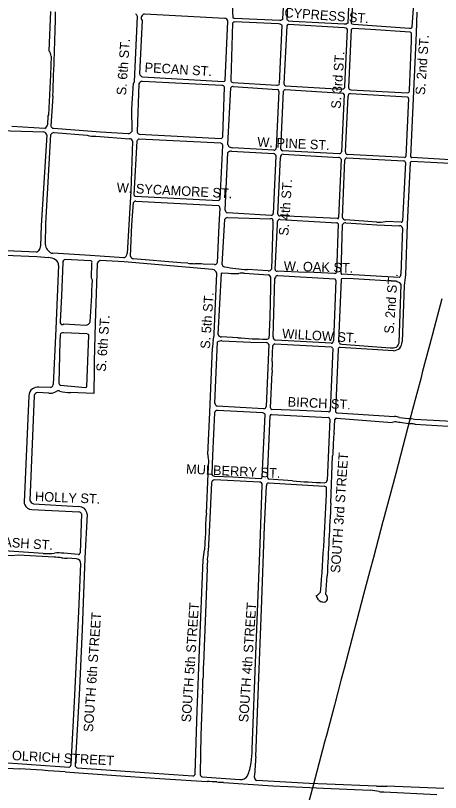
# Model space of a CAD drawing. Extents: x 0 to 712119, y 0 to 761125.
# Drawn here: x 686331 to 688555, y 729358 to 733421 of the extents above; entities that cross this region are included whole.
import ezdxf

# ---------------------------------------------------------------- set-up
doc = ezdxf.new("R2010")
doc.units = 0
for name, color, linetype in [('Arkansas-Missouri Railroad', 7, 'Continuous'), ('PAVED ROADS', 7, 'Continuous'), ('street names', 7, 'Continuous')]:
    doc.layers.add(name, color=color, linetype=linetype)

msp = doc.modelspace()

# ---------------------------------------------------------------- linework, layer by layer
at = {"layer": 'Arkansas-Missouri Railroad'}
msp.add_lwpolyline([(688562.9, 731940.1), (688522.3, 731786.8), (688511.6, 731746.8), (688511.6, 731746.8), (688460.2, 731553.5), (688460.2, 731553.5), (688453.5, 731528.4), (688409, 731360.2), (688409, 731360.2), (688384.7, 731268.3), (688357.9, 731166.8), (688357.9, 731166.8), (688320.9, 731026.5), (688306.8, 730973.4), (688306.8, 730973.4), (688255.4, 730780.1), (688255.4, 730780.1), (688254.2, 730775.6), (688204.3, 730586.7), (688204.3, 730586.7), (688185.6, 730516), (688153, 730393.4), (688153, 730393.4), (688117.3, 730258.8), (688101.8, 730200.1), (688101.8, 730200.1), (688050.7, 730006.7), (688050.7, 730006.7), (688035.8, 729950.2), (687999.7, 729813.3), (687999.7, 729813.3), (687960.2, 729663.3), (687948.6, 729619.9), (687948.6, 729619.9), (687918.6, 729508.1), (687896.9, 729426.7), (687896.9, 729426.7), (687888.3, 729394.3), (687836.8, 729201.1)], dxfattribs=at)
at = {"layer": 'PAVED ROADS'}
for points in [[(687737.6, 733555), (687729, 733403.1), (687728.8, 733398.6), (687721.9, 733396.3), (687719.8, 733394.8), (687714.6, 733394.3), (687477.6, 733405.4), (687474.6, 733405.5), (687471.3, 733405.7), (687470.5, 733408.6), (687468.1, 733441.7), (687474.9, 733589.4)], [(688075.8, 733508.1), (688069.7, 733380.6), (688067.4, 733379.5), (688061.5, 733376.4), (688058.5, 733375.1), (688051.7, 733375.1), (687781.9, 733390.3), (687762, 733392.2), (687757.4, 733394.4), (687754, 733397.3), (687752, 733400.8), (687759.1, 733547.1)], [(688412.9, 733458.7), (688404.5, 733359.3), (688402.7, 733354.9), (688398.1, 733353.3), (688393.5, 733352.8), (688100.1, 733374.7), (688093.8, 733375.6), (688091, 733376.6), (688089.5, 733378.7), (688097.7, 733504.4)], [(686514.4, 733442.8), (686506.1, 733237.2)], [(686954.5, 733075.5), (686968.7, 733415.8)], [(687426.6, 733405.7), (687006.6, 733428.9), (687006.6, 733428.9)], [(688400.4, 732682.7), (688429.5, 733329.2), (688433.6, 733438)], [(686993.5, 733395), (686979.2, 733117)], [(687429.1, 733081.5), (687442.3, 733392)], [(687473.6, 733387.1), (687472, 733386), (687470.4, 733384), (687467.4, 733381.3), (687457.4, 733084.6)], [(687712.5, 733064.7), (687727.3, 733369), (687722.3, 733373.2), (687716.6, 733375.9), (687707.8, 733377.3), (687476.4, 733388.2), (687473.6, 733387.1)], [(688053.9, 733050.8), (688068.2, 733348.6), (688064.7, 733352.5), (688061.3, 733355.3), (688050.3, 733357.4), (687759, 733374.6), (687757.1, 733373.7), (687754.9, 733372.4), (687750.4, 733367.7), (687735.5, 733063.7)], [(688092.9, 733352), (688089.5, 733349.6), (688088.2, 733347.2), (688074.3, 733044.7)], [(688393.7, 733030), (688402.8, 733288.7), (688403.9, 733329.4), (688400.9, 733332.6), (688397, 733334.3), (688189.7, 733347.7), (688097.7, 733353.4), (688092.9, 733352)], [(686517.1, 733208.7), (686513.7, 733111.1)], [(686513.7, 733111.1), (686503.4, 732901.2), (686500.9, 732895.7), (686499.1, 732849.5)], [(686995, 733099.9), (687419.6, 733075.2)], [(686940.9, 732816.1), (686939.6, 732932.6), (686949, 733067.6)], [(686976.1, 733063.6), (686967.5, 732812.6)], [(687410.8, 733055.5), (686994.8, 733076.5)], [(687416.4, 732789.7), (687425.1, 733046)], [(687442.7, 732746.9), (687457.6, 733042.8)], [(687468, 733071), (687697.8, 733056.2)], [(687469.9, 733049.2), (687701, 733034.7)], [(687744.5, 733053.9), (688041.3, 733036.4)], [(686526.1, 732999.8), (686516.6, 732842.9)], [(687709.8, 733025.8), (687695.6, 732728.6)], [(687720, 732721.9), (687734, 733025.1)], [(687742.2, 733033.6), (688043.5, 733015.6)], [(688050.3, 733008.8), (688036.5, 732708.2)], [(688058.6, 732707.8), (688071.9, 732998.6)], [(688083.9, 733012.8), (688380.1, 732995.5)], [(688085.2, 733032.5), (688383.3, 733017.1)], [(688387.8, 732986.9), (688374, 732684.4)], [(686483.6, 732830.6), (686310.9, 732840.4)], [(686186.2, 732821.2), (686479.6, 732812.4)], [(686495.5, 732795.3), (686465.8, 732323.5), (686462.3, 732214.7)], [(686488.6, 732222.6), (686490, 732332.5), (686515.2, 732799)], [(686529.1, 732831.5), (686775.3, 732813.4), (686920.1, 732804)], [(686532.4, 732808.6), (686706.3, 732795.2)], [(686978.9, 732801.2), (687407, 732778.2)], [(686751, 732789.8), (686927.3, 732776.1)], [(686943.9, 732763.9), (686934.2, 732502.1), (686923.7, 732327), (686915.4, 732175.8)], [(686966.6, 732764), (686949.9, 732484.8)], [(687404.8, 732752.9), (686977.8, 732774.9)], [(687401.3, 732462.4), (687415.8, 732741.5)], [(687683.3, 732717), (687467, 732729.9)], [(688027.2, 732698.5), (687728.9, 732714)], [(687428.7, 732402.4), (687441.4, 732702.8)], [(687460.9, 732712), (687682.3, 732700.1)], [(687694.3, 732686.3), (687679.7, 732385.6)], [(687704, 732382.4), (687717.5, 732678.6)], [(687732, 732695.9), (688021.6, 732679.3)], [(688064.8, 732676.7), (688363.7, 732661)], [(688367.5, 732678), (688068, 732694.7)], [(688665.2, 732662.8), (688405.5, 732677.8)], [(688034.7, 732669.8), (688021.8, 732364.3)], [(688043.1, 732364.8), (688054.3, 732666.6)], [(688396.8, 732653.1), (688381.4, 732330.5), (688372.9, 732064.2), (688365, 732009.3), (688354.4, 731713.9)], [(688372.6, 732653.2), (688356.9, 732347.4)], [(688672.1, 732643.9), (688403.5, 732657.9)], [(686956.4, 732475.8), (687395.5, 732453.6)], [(686933.3, 732161.7), (686940.5, 732326.6), (686948, 732442.4)], [(686960.5, 732450.4), (687392.6, 732426.6)], [(687400, 732414), (687395.8, 732324.7), (687385.9, 732128)], [(687669.7, 732376), (687440, 732388.9)], [(687413.2, 732119.1), (687424.3, 732325.5), (687425.7, 732354.3)], [(687440.1, 732365.1), (687665.6, 732358.1)], [(687678.4, 732349.6), (687677, 732326.3), (687670, 732095.2)], [(688016.9, 732358.7), (687715.2, 732373.3)], [(687716.6, 732354.8), (688011.9, 732336.9)], [(688221.6, 732340.8), (688057.9, 732352.7)], [(687689.1, 732092.8), (687701.6, 732328.7), (687702.4, 732343.9)], [(688018.9, 732331.5), (688010.3, 732077)], [(688034.9, 732074.1), (688041.7, 732327.9)], [(688060.5, 732337.1), (688222.7, 732325.9), (688341.2, 732321.6)], [(688349.1, 732340), (688266.9, 732343.2)], [(688356.9, 732308.3), (688348.3, 732068.4)], [(686441.3, 732184), (686163.8, 732196.3)], [(686512.2, 732181.9), (686496.2, 732197.9)], [(686158.2, 732168.7), (686276.7, 732167.9), (686442.8, 732160.2), (686502.8, 732155.5)], [(686898, 732154.2), (686721.4, 732165.3), (686526.1, 732177.7)], [(686724.2, 732138.7), (686590.3, 732145)], [(687233, 732125.2), (687196.1, 732127.9), (686947.3, 732148.5)], [(686556.6, 732113.4), (686541.9, 731782.3), (686528.5, 731490.5)], [(686578.8, 732130), (686571.1, 731955.8), (686565.5, 731820.7), (686565.4, 731814.5)], [(686733.7, 732037.4), (686728.1, 732048.2), (686731, 732127.6)], [(686757.6, 732122), (686748, 731812), (686742.7, 731612.2)], [(687361.8, 732092.4), (686898.9, 732132.3), (686773.9, 732139.4)], [(687373.1, 732119.3), (687312.5, 732120.9)], [(687371.1, 731756.4), (687385.3, 732072.4)], [(687390.8, 731753.1), (687409.7, 732072.7)], [(687412.7, 732075), (687445.5, 732073.1)], [(687527, 732074.3), (687654.3, 732064.4)], [(687653.2, 732085.2), (687544.9, 732092.6)], [(688000.1, 732071.1), (687858.9, 732078.1), (687847.9, 732076.3), (687699.9, 732083.5)], [(688339.1, 732050.4), (688039.6, 732068.1)], [(687678.8, 731740.2), (687688.8, 732046.8)], [(687703.8, 732060.8), (688001.9, 732044.2)], [(688007.5, 732035.3), (687994.5, 731720.2)], [(688035.7, 732039.9), (688021.9, 731719.6)], [(688324.6, 732029.2), (688100, 732043.7), (688042.1, 732045.7)], [(688338.4, 731708.9), (688349.5, 732015), (688343.1, 732023.4)], [(686583.9, 731808.1), (686698.3, 731801.7)], [(686564, 731750.1), (686562.6, 731716.7), (686557.4, 731497.8)], [(686705.8, 731755.4), (686582.2, 731761.9)], [(686704.7, 731481.4), (686715.2, 731747.8), (686715.2, 731747.8)], [(687493.8, 731736.1), (687409.3, 731740.4)], [(687374.3, 731393.8), (687388.7, 731713.9)], [(687411.1, 731720.4), (687562.7, 731712.1)], [(687562.7, 731712.1), (687642.8, 731710.2)], [(687657.2, 731699.6), (687643.1, 731375.9)], [(687688.8, 731703.3), (687982.4, 731688.6)], [(687983.3, 731707.2), (687692.7, 731723.4)], [(688027.2, 731709), (688028.7, 731703.3), (688038.9, 731702.9), (688292.3, 731682.8)], [(687337.8, 731125.9), (687347.8, 731344.1), (687362.2, 731684.5)], [(687673.8, 731612.2), (687677.3, 731695.8)], [(687992.3, 731678.9), (687978.6, 731355.9)], [(688019.2, 731674.4), (688005.3, 731352.7)], [(688309.8, 731667.7), (688029.8, 731684.8)], [(686743.4, 731567.4), (686740.1, 731444.8), (686618.4, 731449)], [(687665.7, 731368.9), (687674, 731554.1)], [(686513.7, 731474.8), (686452.6, 731478)], [(686562.5, 731456.9), (686562.5, 731456.9)], [(686566.6, 731488.1), (686697.9, 731476)], [(686400.2, 731431.9), (686375.6, 730875.8)], [(686427.9, 731434.1), (686406.7, 730884.4)], [(686504.8, 731445.7), (686446.4, 731449)], [(687631.4, 731363.6), (687506.8, 731370.4), (687386.3, 731378.4)], [(687371.9, 731343.3), (687362.6, 731120.3), (687357.8, 731024.8)], [(687625.6, 731342.6), (687388.8, 731355.8)], [(687621.7, 731006.7), (687636.8, 731334.2)], [(687671.3, 731334.2), (687966.6, 731319.5)], [(687968.6, 731347.8), (687817.2, 731354.6), (687672.5, 731360)], [(688015, 731343.1), (688314.2, 731323.3)], [(687649.5, 731008.5), (687663.6, 731327.9)], [(687975.5, 731310.4), (687961.3, 730989.1)], [(687998.3, 731236), (688002.7, 731307.7)], [(688011.8, 731314.9), (688303, 731293)], [(688344.2, 731293.5), (688388.7, 731288.1)], [(688404.2, 731313.3), (688418.4, 731309.7), (688650, 731297.9)], [(688421.9, 731283.1), (688653, 731269)], [(687330.4, 730818.4), (687340.1, 731024.4), (687343.2, 731095.6)], [(687981.5, 730869.9), (687990.9, 731117.9)], [(687371.9, 731012.1), (687468.5, 731007.7), (687614.1, 730999.6)], [(687356.3, 730977.2), (687345.5, 730756.2), (687339.9, 730620)], [(687607.6, 730980.7), (687373.3, 730992.8)], [(687569.9, 729583.1), (687583.8, 729946.1), (687599.7, 730346.5), (687612.1, 730658.2), (687622.4, 730965.5)], [(687655.3, 730976.6), (687947.7, 730958.7)], [(687779.9, 730987), (687656.8, 730996.3)], [(687588.3, 729544.1), (687601.6, 729867.7), (687617.8, 730316.7), (687634.7, 730749.2), (687643.8, 730962)], [(686424.3, 730867.7), (686661.2, 730852.4)], [(686415.5, 730837.9), (686662.6, 730825.2)], [(686705.6, 730813.1), (686694.1, 730582.5), (686679.1, 730211.5), (686665.8, 729901.6), (686643.9, 729500.7)], [(686676.3, 730814.2), (686668.6, 730610.3)], [(686533, 730587.4), (686344.7, 730599), (686312.5, 730595.8), (686092.2, 730612.1), (686092.2, 730612.1), (686092.2, 730612.1)], [(686475.8, 730606.7), (686321.8, 730618.7), (686099.5, 730633.2)], [(686660.1, 730603), (686584.1, 730608.5)], [(687271.3, 729457.1), (687281.3, 729782.2), (687294, 730104.1), (687312.7, 730575), (687320.4, 730626.7)], [(686650.9, 730579.8), (686601.6, 730582.8)], [(686622.3, 729503.8), (686641.9, 729865.8), (686662, 730304.1), (686672, 730552.5)], [(687334.7, 730528.4), (687327.1, 730342.4), (687317.1, 730075)], [(687955.9, 730392.2), (687962.2, 730490.5)], [(687309.8, 729894), (687301.3, 729655.8), (687299.2, 729559.4), (687297.3, 729454.9)], [(686215.9, 729518.1), (686610.9, 729490.3)], [(686047.6, 729496.3), (686148.9, 729492.4), (686351, 729481.2)], [(686591.3, 729464.9), (686711.2, 729456.2), (686906.1, 729443.3), (687112.6, 729428.9), (687333.8, 729414.2)], [(686654.3, 729487.2), (687006.2, 729462.4), (687259.7, 729444.3)], [(687307.5, 729440.1), (687505, 729425.7)], [(687419.2, 729410.5), (687677.1, 729392.9), (687835.5, 729385.6), (687942.6, 729380.1), (688188, 729369.8)], [(688219.7, 729390.1), (687960.5, 729401.8), (687868.5, 729404.5), (687592.2, 729419.9)], [(688573.4, 729378.6), (688275, 729389.7)], [(688259.1, 729360.7), (688537, 729347.1)]]:
    msp.add_lwpolyline(points, dxfattribs=at)
for centre, radius, start, end in [((663739.7, 733994.7), 22808.1, 357.49986, 358.60695), ((686949.8, 733412.8), 19.2, 9.1618, 58.286), ((687010, 733408.1), 21.1, 99.2689, 218.251), ((687427.8, 733391.2), 14.6, 3.0761, 94.6962), ((686450.8, 733199.4), 67, 8.0223, 34.3605), ((687003.9, 733124), 25.7, 195.7653, 249.6327), ((687417.9, 733087.9), 12.8, 277.4042, 330.322), ((687469.6, 733083.1), 12.3, 173.011, 262.7547), ((686944.5, 733076.6), 10, 296.4367, 353.8927), ((686996.7, 733053.6), 22.9, 94.6358, 154.1262), ((687411.8, 733041.5), 14.1, 18.7564, 93.9424), ((687467.1, 733039.6), 10, 73.7422, 161.268), ((687469.9, 733049.2), 0.0000011, 131.8261, 213.3101), ((687699.8, 733069.8), 13.7, 261.866, 337.8968), ((687747.6, 733065.6), 12.2, 188.9947, 255.2436), ((688042, 733048.5), 12.2, 266.6464, 10.7599), ((688086.5, 733044.6), 12.2, 179.3406, 264.2414), ((687700.6, 733025.5), 9.18, 2.1521, 87.7047), ((687742.2, 733025.3), 8.25, 90.28, 181.2573), ((687742.2, 733033.6), 0.000000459, 125.4465, 216.4238), ((688041.2, 733006.6), 9.31, 13.5004, 75.9329), ((688083.4, 733001.1), 11.7, 87.529, 192.3535), ((688382.4, 733028.4), 11.3, 274.5829, 7.8526), ((688380.3, 732988), 7.51, 351.0052, 91.6139), ((686468.1, 732859.1), 32.5, 298.5335, 342.7063), ((686530.2, 732845.3), 13.8, 189.8696, 265.4201), ((686473.5, 732790.7), 22.5, 11.7462, 74.198), ((686532.6, 732787.9), 20.7, 90.6397, 147.468), ((686743.8, 732918.7), 129.1, 253.0931, 273.2007), ((686920, 732828), 24, 270.0625, 330.4883), ((686980.1, 732813.8), 12.7, 185.7973, 264.6254), ((686930.1, 732762.6), 13.8, 5.2641, 101.7343), ((686980.1, 732761.3), 13.8, 99.4524, 168.6655), ((687405, 732789.5), 11.4, 280.0194, 1.3428), ((687403.9, 732741), 11.9, 2.3893, 85.6779), ((687457.4, 732747.5), 14.7, 182.1575, 256.3514), ((687468.3, 732762.3), 32.5, 243.8027, 267.6485), ((687684.4, 732728.2), 11.3, 264.5389, 1.7217), ((687729, 732723.1), 9.12, 187.8359, 269.3649), ((687462, 732684.2), 27.9, 92.3592, 137.9596), ((687676.5, 732682.9), 18.2, 10.8646, 71.3273), ((687731.4, 732681.7), 14.2, 87.3243, 192.5787), ((688020.8, 732664.4), 14.8, 21.007, 86.9823), ((688028.2, 732706.9), 8.39, 263.3011, 9.472), ((688071, 732659.7), 18, 109.8597, 157.5021), ((688069.3, 732705.5), 10.9, 167.9163, 263.0538), ((688364.3, 732687.8), 10.3, 288.2397, 340.76), ((688405.4, 732682.8), 4.99, 181.7658, 271.7039), ((688363.3, 732651.6), 9.37, 9.5136, 87.4724), ((688403.5, 732650.9), 7.02, 89.849, 161.7439), ((686960.5, 732485.6), 10.6, 184.2002, 247.1078), ((686961.1, 732435.6), 14.8, 92.1053, 152.3778), ((687389.4, 732463.9), 12, 300.5709, 352.5152), ((687389.4, 732416.2), 10.9, 347.9045, 72.6052), ((687443.6, 732403.5), 15, 183.9801, 255.9519), ((687445.6, 732342.7), 23.1, 103.7242, 149.7612), ((687668.9, 732349.2), 9.54, 2.6607, 110.2795), ((687669.8, 732385.9), 9.85, 269.364, 358.0687), ((687713.1, 732344.6), 10.7, 71.0499, 184.1993), ((687714.7, 732384.1), 10.8, 188.9318, 272.8171), ((687716.6, 732354.8), 0.000000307, 155.0566, 268.206), ((688017.3, 732363.3), 4.63, 265.0439, 11.8879), ((688055.8, 732365.3), 12.8, 182.1555, 279.4812), ((688350.4, 732346.4), 6.56, 258.2379, 8.005), ((688012.8, 732330.8), 6.23, 7.0972, 97.8996), ((688058.1, 732318.1), 19.1, 82.8678, 149.3543), ((688230.8, 732588.9), 248.3, 267.8757, 278.378), ((688341, 732305.5), 16.1, 9.9177, 89.2425), ((686429.3, 732214.1), 32.4, 291.7288, 327.1462), ((686422, 732217.3), 40.4, 328.9003, 356.2558), ((686523.2, 732219.7), 34.8, 175.2152, 218.8791), ((686496.7, 732072.9), 82.8, 58.6297, 85.7885), ((686526.3, 732203.6), 25.9, 236.8514, 269.4379), ((686522.3, 732114.2), 34.2, 358.6547, 59.2456), ((686592.9, 732131.1), 14.1, 100.7733, 184.2543), ((686891.1, 732177.6), 24.4, 286.4247, 355.8827), ((686951.3, 732166.8), 18.7, 195.9936, 257.8231), ((686723.2, 732130.5), 8.32, 339.7481, 83.1954), ((686785.8, 732112), 29.9, 113.323, 160.5148), ((687276.7, 732580.3), 457.2, 264.5167, 269.1634), ((687274.9, 731806.9), 316.2, 83.177, 90.8822), ((687375.3, 732129.8), 10.7, 258.4698, 350.2504), ((687423.4, 732117.5), 10.3, 171.4813, 274.7666), ((687574.7, 732838), 746, 258.3619, 267.7049), ((687359, 732065.3), 27.3, 15.2152, 83.9355), ((687414.8, 732069.1), 6.31, 109.6154, 145.3708), ((687477.4, 732422.1), 350.5, 264.7669, 273.6493), ((687521.1, 731965.4), 109, 86.9067, 101.3004), ((687654.7, 732101.7), 16.6, 264.8844, 336.9546), ((687652.2, 732049.6), 14.9, 350.7217, 81.9466), ((687700.4, 732095.1), 11.5, 191.5395, 267.7245), ((687999.8, 732083.5), 12.4, 271.5539, 328.0532), ((688039.9, 732073.1), 5.1, 169.4522, 266.4109), ((688325.6, 732068.7), 22.7, 306.4261, 359.371), ((665948.5, 733022.5), 20808.5, 356.68447, 357.28658), ((681230.5, 732058.4), 6436.6, 357.12783, 359.90003), ((687707, 732042.4), 18.7, 99.7091, 166.1886), ((687703.8, 732060.8), 0.00000149, 162.4192, 238.3628), ((687996.2, 732034.4), 11.4, 4.2025, 59.7547), ((688042.2, 732039.2), 6.5, 90.5124, 173.5126), ((688319.6, 731980.9), 48.6, 61.1231, 84.1622), ((686696.9, 731828.7), 27, 272.9682, 339.0287), ((686576.2, 731815.7), 10.8, 186.5825, 315.2937), ((686579.1, 731746.7), 15.5, 78.4552, 167.2145), ((686706.7, 731746.8), 8.61, 6.1261, 95.7883), ((686880.5, 731817), 494.3, 348.7611, 352.959), ((687410.3, 731761.6), 21.3, 203.6903, 267.3668), ((687695, 731739.5), 16.2, 177.4216, 262.1521), ((687602.7, 731682), 240.5, 170.7547, 179.4118), ((687420.3, 731647.9), 73.2, 97.2228, 115.5494), ((687645.1, 733363.6), 1634.5, 264.6881, 269.9881), ((687641, 731692.6), 17.7, 23.249, 84.0569), ((687646.3, 731743.9), 14.9, 264.0021, 327.7373), ((687691.7, 731686.5), 17.1, 99.8217, 147.1213), ((687688.8, 731703.3), 0.000000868, 28.6197, 101.2131), ((687983.8, 731718.1), 10.9, 267.3082, 11.3653), ((687987.9, 731696), 41.5, 18.3198, 34.8216), ((688298.2, 731719.2), 41.5, 309.7393, 345.6242), ((688296.9, 731718), 57.7, 321.3429, 355.9405), ((687970.5, 731666.4), 25.1, 29.7968, 61.8272), ((688029.2, 731674.8), 9.99, 86.6745, 182.4504), ((688300, 731746.9), 64.6, 263.1466, 292.547), ((688306.3, 731718.9), 51.3, 273.8416, 313.9536), ((686941, 731606.6), 198.4, 178.3697, 185.7518), ((686527.8, 731578.5), 215.9, 357.045, 2.1798), ((687864.1, 731572.6), 190.9, 176.3997, 185.5367), ((689812.8, 731573.2), 2139.3, 178.956, 179.6958), ((686568.7, 731499.2), 11.3, 187.112, 259.4042), ((686445, 731431.3), 44.8, 124.4194, 179.1393), ((686452.8, 731416.4), 61.6, 90.2146, 122.6136), ((686510.1, 731493.1), 18.6, 281.3592, 352.0853), ((686520.7, 731492.5), 44.3, 295.0109, 306.8928), ((686554.8, 731441), 17.7, 64.031, 114.8894), ((686624.3, 731692.2), 243.3, 255.2921, 268.6193), ((686694.9, 731486.8), 11.2, 285.916, 331.2282), ((686452.5, 731422.7), 27.1, 102.8862, 154.9975), ((686511.1, 731507.1), 61.7, 264.1633, 297.3612), ((687391.9, 731395.1), 17.6, 184.293, 251.4211), ((687626.8, 731379.6), 16.6, 286.0985, 347.1632), ((687389.7, 731336.9), 18.9, 92.5793, 160.0444), ((687626, 731331.5), 11.2, 13.9386, 91.9243), ((687670.8, 731326.9), 7.34, 86.072, 171.7549), ((687674.1, 731368.2), 8.4, 175.6491, 258.9556), ((687970.1, 731356.3), 8.57, 260.0864, 357.3861), ((688014.9, 731352.7), 9.59, 180.187, 270.4017), ((687964.6, 731308.7), 11, 8.9641, 79.5594), ((688011.2, 731306.3), 8.63, 85.8965, 171.0034), ((688320.7, 731236.8), 58.9, 81.883, 107.5068), ((688316.2, 731261.8), 61.5, 66.1469, 91.8846), ((688363.1, 731539.2), 246.4, 262.0469, 265.5848), ((688420.6, 731959.1), 646, 262.9315, 268.5499), ((688401.8, 731343), 56.4, 256.5409, 271.5746), ((687549.5, 726706.3), 4659.3, 79.2083, 79.4397), ((688136.2, 731205.3), 141.3, 167.4194, 182.0628), ((691523.5, 730984.5), 3535.1, 176.5028, 177.838), ((687513.1, 731129.8), 175.4, 181.2918, 186.5977), ((686902.6, 730969.6), 458.2, 15.9647, 17.7979), ((687371.9, 731026.4), 14.3, 186.5051, 269.7951), ((687614.4, 731006.9), 7.3, 267.7496, 358.3435), ((687659.6, 731006.3), 10.3, 167.6191, 254.743), ((687374.2, 730974.7), 18.1, 92.9066, 172.1093), ((687609.5, 730967.8), 13.1, 349.9213, 98.3816), ((687657.9, 730962.7), 14.1, 100.4955, 182.8111), ((688119.3, 735479.8), 4505.6, 265.6794, 267.8128), ((687948.4, 730990.4), 12.9, 265.3479, 354.634), ((673613.5, 731503.9), 14356.4, 355.61384, 357.78761), ((687948.5, 730947.8), 10.9, 9.7988, 94.2677), ((686430.3, 730891.7), 24.7, 197.1101, 256.1065), ((686414.9, 730878.7), 39.4, 184.2555, 204.2325), ((686415.3, 730877.1), 39.2, 201.8703, 270.2989), ((686663.6, 730810.4), 42.1, 3.6982, 93.2956), ((747473.6, 727648.3), 59579.3, 176.900321, 177.265638), ((686660.7, 730808.8), 16.6, 19.1114, 83.5162), ((687778.1, 730749.4), 453, 171.2395, 183.9294), ((689062, 730564), 1742.7, 174.9178, 177.9397), ((686466.2, 731570.3), 963.6, 270.5726, 274.1108), ((686556.7, 730389.2), 221, 82.8741, 95.5681), ((686662.2, 730609.2), 6.53, 251.8364, 9.7079), ((687166.8, 730613.3), 173.3, 348.369, 2.2046), ((686536.6, 730340.2), 247.3, 81.7295, 90.8407), ((686603.5, 730817.1), 234.3, 262.3039, 269.5165), ((686646.7, 730554.8), 25.4, 354.9855, 80.5711), ((686986.6, 730566.2), 350.1, 353.8094, 1.996), ((687829, 730497.1), 134.6, 304.2256, 317.3293), ((687940.8, 730391.5), 36.6, 188.8161, 250.4354), ((687945.1, 730395.1), 41.5, 246.4368, 279.0591), ((687942.1, 730374.5), 22.5, 295.1062, 52.1559), ((691048.3, 729856.3), 3737.6, 176.6451, 178.5553), ((685614.7, 729984), 1697.6, 356.9591, 358.8691), ((686468.4, 729640.3), 1103, 353.3445, 357.0256), ((734667.9, 726074.2), 47207.2, 175.78473, 175.91177), ((686607.5, 729504.7), 14.8, 283.0019, 356.5755), ((687269.4, 729556.9), 297.9, 337.9026, 351.4191), ((685520.2, 715438.7), 14067.1, 85.63328, 86.6141), ((686654.8, 729498.3), 11.2, 167.6559, 267.5733), ((687259.7, 729456), 11.6, 269.9202, 5.3841), ((687312.5, 729454.5), 15.2, 178.3251, 250.831), ((687509.8, 729467.8), 42.3, 263.448, 327.2365), ((687608.3, 729442.4), 27.6, 185.4333, 234.4639), ((687329.7, 728596.5), 817.8, 86.0912, 89.7096), ((687693.2, 734791.5), 5387.9, 266.7253, 267.0849), ((688219.6, 730900.2), 1510.1, 270.0008, 271.1161), ((688273.4, 729861.6), 471.8, 267.0386, 270.1946), ((687867.4, 727320.9), 2073.8, 79.8262, 81.1076), ((688257.4, 729552.5), 191.9, 262.9031, 270.484)]:
    msp.add_arc(centre, radius, start, end, dxfattribs=at)

# ---------------------------------------------------------------- texts
at = {"layer": 'street names'}
for s, rotation, p in [('CYPRESS ST.', 355.9069, (687737.1, 733412.3)), ('S. 6th ST.', 86.0169, (686909.4, 733002.6)), ('S. 2nd ST.', 86.0169, (688473.5, 733003.8)), ('S. 3rd ST.', 86.0169, (688032.1, 732931.8)), ('PECAN ST.', 356.59, (687005.3, 733125.3)), ('W. PINE ST.', 357.3474, (687595.9, 732735.5)), ('S. 4th ST.', 86.0169, (687758.5, 732268.1)), ('W. SYCAMORE ST.', 357.0105, (686859.6, 732496.7)), ('W. OAK ST.', 358.3605, (687734.4, 732086.3)), ('S. 2nd ST.', 86.0169, (688309.9, 731755.5)), ('S. 5th ST.', 86.0169, (687348.1, 731676.3)), ('S. 6th ST.', 86.0169, (686803.3, 731557)), ('WILLOW ST.', 356.6063, (687725.2, 731733.1)), ('BIRCH ST.', 357.3285, (687754.5, 731376.2)), ('SOUTH 3rd STREET', 86.0612, (688029.5, 730503.8)), ('MULBERRY ST.', 357.4331, (687222.7, 731024.8)), ('HOLLY ST.', 357.6587, (686432.1, 730881.6)), ('W. ASH ST.', 356.1989, (686165.6, 730649.7)), ('SOUTH 5th STREET', 86.0612, (687248.6, 729723)), ('SOUTH 4th STREET', 86.0612, (687548.6, 729723)), ('SOUTH 6th STREET', 86.0612, (686736.1, 729672.2)), ('WEST OLRICH STREET', 356.9997, (686099.9, 729538.1))]:
    msp.add_text(s, height=50, rotation=rotation, dxfattribs=at).set_placement(p)

doc.saveas('drawing.dxf')
